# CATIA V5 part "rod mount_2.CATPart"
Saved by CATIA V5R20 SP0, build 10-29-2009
Part number: rod mount 2
Source: Unknown
Bounding box of the stored display mesh (mm): x 0 to 15, y -10 to 58.3, z -46 to 0
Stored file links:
  C:\Users\Ikarus\OneDrive - FH JOANNEUM\BAC - Arbeit 1\CAD Modell\CAD-Modell-Step files\rod mount\rod mount_2.CATPart
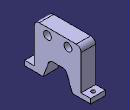
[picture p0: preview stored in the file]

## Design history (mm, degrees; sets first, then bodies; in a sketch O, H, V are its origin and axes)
Body1 (main body)
  Solid1 "Hauptkörper": solid without history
